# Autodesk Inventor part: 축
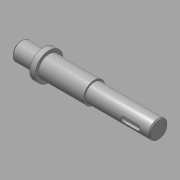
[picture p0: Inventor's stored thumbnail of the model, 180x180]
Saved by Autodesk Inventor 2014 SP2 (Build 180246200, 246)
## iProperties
Created: 2015-09
Part Number: 축
Material: 강철, 연강
Document SubType Name: Modeling
Designer: mduedu
Density: 7.86 g/cm^3
Mass: 263.424 g
Surface Area: 86.4309 cm^2
Volume: 33.5145 cm^3
Appearance: 강철
Author: mduedu
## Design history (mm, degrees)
sketch "스케치1"
  geometry: L1 (-64, 0)-(64, 0); L2 (-64, 0)-(-64, 8.5); L3 (-64, 8.5)-(-43, 8.5); L4 (-43, 8.5)-(-43, 13); L5 (-43, 13)-(-38, 13); L6 (-38, 13)-(-38, 10); L7 (-38, 10)-(4, 10); L8 (4, 10)-(4, 8.5); L9 (4, 8.5)-(64, 8.5); L10 (64, 8.5)-(64, 0); 2 further points
  constraints: 20 end point, 5 parallel, 2 horizontal, 2 perpendicular, 1 coincident, 1 midpoint, 1 vertical
  dimensions: "d0" = 128 distance of L1.start L1.end; "d2" = 5 distance of L4.end L5.end; "d3" = 42 distance of L6.end L7.end; "d4" = 60 distance of L8.end L9.end; "d5" = 17 diameter of L3 L1; "d6" = 17 diameter of L9 L1; "d7" = 20 diameter of L7 L1; "d8" = 26 diameter of L5 L1
revolve "회전1" sketch "스케치1" stored, may be unused: angle "d9" = 90 deg
node "작업 평면1"
sketch "스케치2"
  geometry: L1 (5.5, 2.5)-(18.5, 2.5); L2 (18.5, -2.5)-(5.5, -2.5); L3 (5.5, 2.5)-(18.5, -2.5); L4 (18.5, 2.5)-(5.5, -2.5); L5 (30, -8.5)-(30, 8.5) reference; A1 r 2.5 centre (5.5, 0) between (5.5, 2.5) and (5.5, -2.5); A2 r 2.5 centre (18.5, 0) between (18.5, -2.5) and (18.5, 2.5); 2 further points
  constraints: 8 end point, 4 point on circle, 4 tangent, 2 centre point, 2 midpoint, 1 horizontal, 1 horizontal alignment, 1 parallel
  dimensions: "d10" = 18 dimension on A2 A1; "d12" = 9 distance edge to line of A2 L5; "d13" = 5 distance between parallel lines of L2 L1
extrude "돌출1" cut sketch "스케치2" distance "d14" = 3; taper "d15" = 0 deg
node "작업 평면2"
sketch "스케치4"
  geometry: L1 (7, -3)-(-9, -3); L2 (-9, 3)-(7, 3); L3 (-21, 10)-(-21, -10) reference; A1 r 3 centre (-9, 0) between (-9, 3) and (-9, -3); A2 r 3 centre (7, 0) between (7, -3) and (7, 3); 1 further point
  constraints: 4 end point, 4 point on circle, 4 tangent, 2 centre point, 1 horizontal, 1 horizontal alignment, 1 parallel
  dimensions: "d16" = 22 dimension on A1 A2; "d18" = 6 distance between parallel lines of L2 L1; "d19" = 9 distance edge to line of A1 L3
extrude "돌출2" cut sketch "스케치4" distance "d20" = 3.5; taper "d21" = 0 deg
sketch "스케치5"
  geometry: L1 (4, 8.5)-(64, 8.5) reference; L2 (4, -8.5)-(64, -8.5) reference; L3 (37, 8.5)-(37, -8.5); L4 (37, -6.5)-(35, -8.5); L5 (37, -8.5)-(35, -8.5); L6 (37, -8.5)-(37, -6.5); L7 (4, -10)-(4, 10) reference; 1 further point
  constraints: 8 end point, 4 point on line, 1 collinear, 1 perpendicular
  dimensions: "d22" = 4 diameter of L4.end L3; "d24" = 45 deg angle of L3 L4; "d26" = 33 distance between parallel lines of L3 L7
revolve "회전2" sketch "스케치5" stored, may be unused: angle "d27" = 90 deg
chamfer "모따기1" distance "d28" = 1; stored, may be unused: second distance "d29" = 2, angle "d30" = 45 deg
sketch "스케치6"
  geometry: L1 (37, -6.5)-(35, -8.5) reference; L2 (37, -6.5)-(39, -8.5) reference; 2 further points
  constraints: 1 coincident
node "솔리드1"
